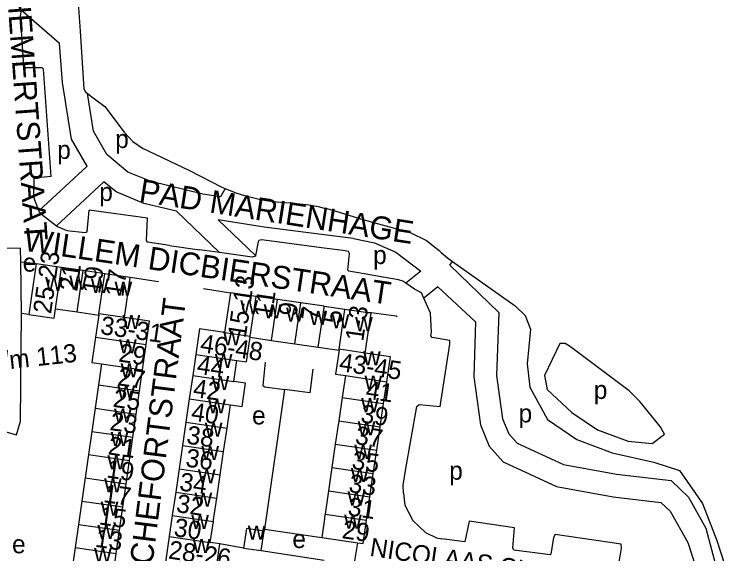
# Model space of a CAD drawing. Extents: x 160673 to 161924, y 382258 to 384145.
# Drawn here: x 161759.3 to 161915.9, y 383393.3 to 383511.4 of the extents above; entities that cross this region are included whole.
import ezdxf

# ---------------------------------------------------------------- set-up
doc = ezdxf.new("R2010")
doc.units = 0
for name, color, linetype in [('BLT_Basislijn', 7, 'Continuous'), ('BLT_Bebouwing', 7, 'Continuous'), ('BLT_Centroide', 7, 'Continuous'), ('BLT_Huisnummer', 7, 'Continuous'), ('BLT_Huisnummer_ tussenligend', 7, 'Continuous'), ('BLT_Huisnummer_reeks', 7, 'Continuous'), ('BLT_Huisnummer_zonder_bebouwing', 7, 'Continuous'), ('BLT_Onderverdeling_panden', 7, 'Continuous'), ('BLT_Straatnaam', 7, 'Continuous'), ('BLT_Straatnaam_verkleind', 7, 'Continuous')]:
    doc.layers.add(name, color=color, linetype=linetype)

msp = doc.modelspace()

# ---------------------------------------------------------------- linework, layer by layer
at = {"layer": 'BLT_Basislijn'}
for p, q in [((161773.73, 383507.7), (161774.58, 383495.12)), ((161775.28, 383478.13), (161764.67, 383468.34)), ((161778.95, 383474.72), (161768.55, 383465.12)), ((161805.49, 383473.25), (161804.45, 383471.41)), ((161804.74, 383473.57), (161805.49, 383473.25)), ((161763.77, 383470.76), (161764.67, 383468.34)), ((161794.79, 383468.29), (161804.2, 383459.25)), ((161803.95, 383466.43), (161812.11, 383458.59)), ((161845.97, 383463.66), (161849.51, 383461.89)), ((161793.31, 383460.79), (161799.89, 383459.86)), ((161764.11, 383456.74), (161760.73, 383457.16)), ((161760.91, 383445.86), (161760.73, 383457.16)), ((161854.64, 383456.49), (161855.21, 383457.31)), ((161848.28, 383455.15), (161844.99, 383452.51)), ((161790.9, 383452.81), (161784.67, 383453.8)), ((161800.73, 383451.38), (161806.64, 383450.45)), ((161848.96, 383449.28), (161848.46, 383450.45)), ((161852.04, 383451.76), (161848.96, 383449.28)), ((161852.04, 383451.76), (161860.27, 383444.06)), ((161762.52, 383445.67), (161760.91, 383445.86)), ((161818.46, 383429.21), (161814.05, 383398.67)), ((161814.05, 383398.67), (161813.99, 383398.21)), ((161814.05, 383398.67), (161826.6, 383396.85)), ((161910.64, 383398.88), (161914.28, 383385.18)), ((161833.69, 383390.85), (161834.53, 383395.69)), ((161809.5, 383394.52), (161804.33, 383395.43)), ((161813.36, 383393.96), (161827.12, 383391.85))]:
    msp.add_line(p, q, dxfattribs=at)
for points in [[(161769.48, 383567.91), (161770.84, 383548.66), (161773.73, 383507.7)], [(161767.42, 383475.92), (161765.69, 383499.42), (161765.46, 383499.68), (161761.6, 383499.66), (161761.44, 383500.07), (161760.72, 383511.06), (161760.94, 383512.21)], [(161769.9, 383496.48), (161769.19, 383505.02), (161760.94, 383512.21)], [(161775.28, 383478.13), (161771.83, 383484.08), (161769.9, 383496.48)], [(161774.58, 383495.12), (161774.93, 383494.4), (161775.33, 383494.09)], [(161804.45, 383471.41), (161800.59, 383472.04), (161789.26, 383474.76), (161784.21, 383476.87), (161779.57, 383480.68), (161776.63, 383485.78), (161775.33, 383494.09)], [(161775.33, 383494.09), (161776.89, 383492.92), (161779.13, 383491.2), (161783.37, 383485.58), (161785.3, 383483.55), (161787.4, 383482.08), (161797.7, 383477.21), (161804.74, 383473.57)], [(161767.42, 383475.92), (161763.57, 383475.53), (161763.52, 383471.55), (161763.77, 383470.76)], [(161794.79, 383468.29), (161787.7, 383469.99), (161781.6, 383472.54), (161778.95, 383474.72)], [(161805.49, 383473.25), (161806.38, 383472.88), (161808.05, 383472.26), (161809.74, 383471.72), (161811.46, 383471.26), (161813.19, 383470.87), (161814.94, 383470.57), (161816.7, 383470.34), (161818.47, 383470.19), (161819.84, 383470.13)], [(161819.84, 383470.13), (161821.84, 383469.93), (161823.82, 383469.65), (161825.79, 383469.29), (161827.12, 383468.99)], [(161764.67, 383468.34), (161764.72, 383468.2), (161765.26, 383467.62), (161768.55, 383465.12)], [(161769.82, 383464.48), (161770.81, 383464.07), (161774.87, 383463.65), (161775.3, 383463.76), (161775.75, 383468.54)], [(161793.31, 383460.79), (161788.46, 383461.51), (161788.25, 383461.86), (161788.48, 383466.8), (161775.75, 383468.54)], [(161827.12, 383468.99), (161827.74, 383468.85), (161829.67, 383468.33), (161831.15, 383467.88)], [(161831.15, 383467.88), (161835.09, 383466.65), (161839.05, 383465.49), (161843.03, 383464.41), (161845.97, 383463.66)], [(161827.12, 383463.12), (161813.99, 383464.79), (161803.95, 383466.43)], [(161768.55, 383465.12), (161768.91, 383464.84), (161769.82, 383464.48)], [(161833.55, 383462.3), (161827.12, 383463.12)], [(161827.12, 383460.19), (161813.39, 383462.01), (161812.84, 383461.85), (161812.68, 383461.58), (161812.11, 383458.59)], [(161833.55, 383462.3), (161838.17, 383461.39), (161842.8, 383459.29), (161848.28, 383455.15)], [(161849.51, 383461.89), (161850.91, 383460.81), (161852.27, 383459.67), (161852.76, 383459.24)], [(161760.73, 383457.16), (161760.68, 383460.22), (161757.04, 383460.11)], [(161804.2, 383459.25), (161799.89, 383459.86)], [(161843.43, 383453.29), (161832.51, 383455.14), (161832.35, 383455.36), (161832.67, 383459.04), (161832.46, 383459.43), (161831.23, 383459.65), (161827.12, 383460.19)], [(161812.11, 383458.59), (161812.08, 383458.44), (161811.35, 383458.23), (161804.2, 383459.25)], [(161852.76, 383459.24), (161854.16, 383458.06), (161855.21, 383457.31)], [(161855.21, 383457.31), (161868.9, 383447.57)], [(161854.64, 383456.49), (161865.34, 383446.1), (161864.87, 383432.31), (161866.19, 383422.83), (161867.54, 383419.57), (161869.37, 383417.51), (161879.51, 383412.83), (161891.11, 383410.67), (161903.04, 383409.3), (161906.83, 383405.7), (161910.64, 383398.88)], [(161844.99, 383452.51), (161844.32, 383452.96), (161843.43, 383453.29)], [(161848.46, 383450.45), (161846.9, 383451.23), (161844.99, 383452.51)], [(161844.94, 383411.51), (161847.42, 383425.5), (161847.9, 383425.93), (161852.49, 383425.5), (161854.66, 383439.16), (161854.66, 383439.95), (161850.77, 383440.66), (161850.45, 383441.02), (161850.64, 383441.77), (161850.37, 383445.93), (161848.96, 383449.28)], [(161868.9, 383447.57), (161871.11, 383445.45), (161872.28, 383442.49), (161871.58, 383434.88), (161872.11, 383429.73), (161875.98, 383422.7), (161882.42, 383418.32), (161890.17, 383415.35), (161899.31, 383413.34), (161904.86, 383411.54), (161909.91, 383404.26), (161913.04, 383396.17)], [(161751.76, 383403.06), (161756.44, 383420.27), (161759.83, 383419.35), (161760.67, 383422.31), (161760.91, 383445.86)], [(161843.12, 383445.13), (161842.91, 383445.3), (161837.41, 383446.03)], [(161860.27, 383444.06), (161859.86, 383432.05), (161861.33, 383421.51), (161863.25, 383416.87), (161866.33, 383413.41), (161877.98, 383408.03), (161890.36, 383405.72), (161900.81, 383404.52), (161902.83, 383402.6), (161906.69, 383395.71)], [(161814.24, 383435.22), (161813.7, 383430.09), (161814.18, 383429.82), (161818.46, 383429.21)], [(161824.69, 383433.7), (161824.03, 383428.54), (161818.46, 383429.21)], [(161844.48, 383406.57), (161844.45, 383408.31), (161844.94, 383411.51)], [(161844.48, 383406.57), (161844.78, 383403.95), (161846.53, 383400.54), (161849.3, 383397.9), (161851.74, 383396.77), (161852.92, 383396.53)], [(161858.84, 383400.41), (161857.91, 383395.86), (161852.92, 383396.53)], [(161906.73, 383383.61), (161905.69, 383387.62), (161900, 383388.49), (161891.56, 383390.53), (161892.17, 383394.49), (161892.14, 383395.41), (161877.7, 383397.48), (161877.33, 383396.85), (161876.77, 383393.18), (161876.62, 383393.02), (161868.62, 383394.06), (161868.41, 383394.58), (161868.79, 383398.92), (161858.84, 383400.41)], [(161906.69, 383395.71), (161908.37, 383390.55), (161909.71, 383382.11), (161909.71, 383375.2), (161910.5, 383367.55), (161911.76, 383360.3), (161913.12, 383353.69), (161913.12, 383350.66), (161912.25, 383346.91)], [(161913.04, 383396.17), (161914.76, 383391.02), (161915.88, 383385.88)]]:
    msp.add_lwpolyline(points, dxfattribs=at)
msp.add_lwpolyline([(161878.7, 383439.34), (161875.34, 383432.33), (161875.93, 383429.28), (161881.3, 383424.18), (161886.96, 383420.4), (161893.66, 383417.95), (161898.94, 383417.45), (161901.58, 383419.45), (161900.66, 383421.17), (161896.18, 383426.59), (161893.9, 383428.92), (161881.01, 383438.58), (161879.9, 383439.35)], close=True, dxfattribs=at)
at = {"layer": 'BLT_Bebouwing'}
for p, q in [((161769.63, 383455.95), (161764.11, 383456.74)), ((161774.39, 383455.27), (161769.63, 383455.95)), ((161779.12, 383454.59), (161774.39, 383455.27)), ((161784.67, 383453.8), (161779.12, 383454.59)), ((161783.41, 383445.01), (161784.67, 383453.8)), ((161806.64, 383450.45), (161805.36, 383441.74)), ((161812.23, 383449.63), (161806.64, 383450.45)), ((161816.89, 383448.95), (161812.23, 383449.63)), ((161822.02, 383448.2), (161816.89, 383448.95)), ((161827.12, 383447.46), (161822.02, 383448.2)), ((161827.15, 383447.45), (161827.12, 383447.46)), ((161831.68, 383446.79), (161827.15, 383447.45)), ((161768.33, 383446.9), (161773.09, 383446.22)), ((161773.09, 383446.22), (161777.82, 383445.54)), ((161836.12, 383437.2), (161837.41, 383446.03)), ((161777.82, 383445.54), (161777.13, 383440.72)), ((161810.92, 383440.68), (161815.58, 383440)), ((161815.58, 383440), (161820.71, 383439.25)), ((161787.39, 383433.58), (161788.19, 383439.13)), ((161820.71, 383439.25), (161825.84, 383438.5)), ((161799.06, 383436.94), (161798.38, 383432.32)), ((161841.62, 383436.4), (161836.12, 383437.2)), ((161840.83, 383430.96), (161841.62, 383436.4)), ((161778.44, 383434.86), (161777.78, 383430.24)), ((161807.37, 383431.01), (161808.05, 383435.62)), ((161786.73, 383428.96), (161787.39, 383433.58)), ((161798.38, 383432.32), (161797.63, 383427.22)), ((161831.77, 383432.28), (161831.08, 383427.5)), ((161777.78, 383430.24), (161777.05, 383425.15)), ((161840.13, 383426.18), (161840.83, 383430.96)), ((161786, 383423.87), (161786.73, 383428.96)), ((161797.63, 383427.22), (161796.89, 383422.11)), ((161831.08, 383427.5), (161830.33, 383422.39)), ((161805.88, 383420.8), (161806.62, 383425.9)), ((161839.39, 383421.07), (161840.13, 383426.18)), ((161777.05, 383425.15), (161776.32, 383420.07)), ((161785.27, 383418.78), (161786, 383423.87)), ((161830.33, 383422.39), (161829.58, 383417.28)), ((161796.89, 383422.11), (161796.14, 383417)), ((161805.13, 383415.69), (161805.88, 383420.8)), ((161838.64, 383415.96), (161839.39, 383421.07)), ((161776.32, 383420.07), (161775.59, 383414.98)), ((161784.54, 383413.69), (161785.27, 383418.78)), ((161796.14, 383417), (161795.4, 383411.89)), ((161829.58, 383417.28), (161828.84, 383412.17)), ((161837.89, 383410.85), (161838.64, 383415.96)), ((161775.59, 383414.98), (161774.87, 383409.89)), ((161804.39, 383410.58), (161805.13, 383415.69)), ((161783.81, 383408.61), (161784.54, 383413.69)), ((161795.4, 383411.89), (161794.65, 383406.78)), ((161828.84, 383412.17), (161828.09, 383407.07)), ((161774.87, 383409.89), (161774.14, 383404.8)), ((161803.64, 383405.47), (161804.39, 383410.58)), ((161837.15, 383405.74), (161837.89, 383410.85)), ((161783.09, 383403.52), (161783.81, 383408.61)), ((161794.65, 383406.78), (161793.9, 383401.68)), ((161828.09, 383407.07), (161827.34, 383401.96)), ((161836.4, 383400.63), (161837.15, 383405.74)), ((161774.14, 383404.8), (161773.41, 383399.71)), ((161782.36, 383398.43), (161783.09, 383403.52)), ((161793.9, 383401.68), (161793.23, 383397.06)), ((161802.22, 383395.74), (161802.89, 383400.36)), ((161773.41, 383399.71), (161772.68, 383394.62)), ((161781.63, 383393.34), (161782.36, 383398.43)), ((161813.36, 383393.96), (161813.99, 383398.21)), ((161793.23, 383397.06), (161792.41, 383391.46)), ((161804.33, 383395.43), (161802.22, 383395.74)), ((161826.6, 383396.85), (161827.12, 383396.77)), ((161827.12, 383396.77), (161834.53, 383395.69)), ((161772.68, 383394.62), (161771.95, 383389.54)), ((161809.5, 383394.52), (161813.36, 383393.96)), ((161780.9, 383388.26), (161781.63, 383393.34))]:
    msp.add_line(p, q, dxfattribs=at)
for points in [[(161764.11, 383456.74), (161763.4, 383451.79), (161762.52, 383445.67)], [(161762.52, 383445.67), (161768.04, 383444.88), (161768.33, 383446.9)], [(161837.41, 383446.03), (161836.71, 383446.06), (161831.68, 383446.79)], [(161788.19, 383439.13), (161788.92, 383444.22), (161783.41, 383445.01)], [(161805.36, 383441.74), (161799.87, 383442.54), (161799.06, 383436.94)], [(161777.13, 383440.72), (161776.33, 383435.17), (161778.44, 383434.86)], [(161808.05, 383435.62), (161810.14, 383435.32), (161810.92, 383440.68)], [(161825.84, 383438.5), (161830.42, 383437.83)], [(161830.42, 383437.83), (161829.65, 383432.59), (161831.77, 383432.28)], [(161806.62, 383425.9), (161809.19, 383425.53), (161809.93, 383430.64), (161807.37, 383431.01)], [(161802.89, 383400.36), (161802.94, 383400.69), (161803.64, 383405.47)], [(161827.34, 383401.96), (161827.32, 383401.8), (161827.12, 383400.4)], [(161827.12, 383400.4), (161826.6, 383396.85)], [(161834.53, 383395.69), (161835.65, 383395.52), (161836.4, 383400.63)], [(161813.99, 383398.21), (161810.13, 383398.78), (161809.5, 383394.52)], [(161792.41, 383391.46), (161803.51, 383389.84), (161804.33, 383395.43)]]:
    msp.add_lwpolyline(points, dxfattribs=at)
at = {"layer": 'BLT_Onderverdeling_panden'}
for p, q in [((161768.33, 383446.9), (161769.63, 383455.95)), ((161773.09, 383446.22), (161774.39, 383455.27)), ((161777.86, 383445.81), (161779.12, 383454.59)), ((161810.96, 383440.92), (161812.23, 383449.63)), ((161815.58, 383440), (161816.89, 383448.95)), ((161820.71, 383439.25), (161822.02, 383448.2)), ((161825.84, 383438.5), (161827.12, 383447.23)), ((161827.12, 383447.23), (161827.15, 383447.45)), ((161777.82, 383445.54), (161777.86, 383445.81)), ((161783.41, 383445.01), (161777.86, 383445.81)), ((161805.36, 383441.74), (161810.96, 383440.92)), ((161810.92, 383440.68), (161810.96, 383440.92)), ((161777.13, 383440.72), (161788.19, 383439.13)), ((161830.42, 383437.83), (161830.42, 383438.11)), ((161799.06, 383436.94), (161808.05, 383435.62)), ((161778.44, 383434.86), (161787.39, 383433.58)), ((161798.38, 383432.32), (161807.37, 383431.01)), ((161831.77, 383432.28), (161840.83, 383430.96)), ((161777.78, 383430.24), (161786.73, 383428.96)), ((161797.63, 383427.22), (161806.62, 383425.9)), ((161831.08, 383427.5), (161840.13, 383426.18)), ((161777.05, 383425.15), (161786, 383423.87)), ((161830.33, 383422.39), (161839.39, 383421.07)), ((161796.89, 383422.11), (161805.88, 383420.8)), ((161776.32, 383420.07), (161785.27, 383418.78)), ((161796.14, 383417), (161805.13, 383415.69)), ((161829.58, 383417.28), (161838.64, 383415.96)), ((161775.59, 383414.98), (161784.54, 383413.69)), ((161795.4, 383411.89), (161804.39, 383410.58)), ((161828.84, 383412.17), (161837.89, 383410.85)), ((161774.87, 383409.89), (161783.81, 383408.61)), ((161794.65, 383406.78), (161803.64, 383405.47)), ((161828.09, 383407.07), (161837.15, 383405.74)), ((161774.14, 383404.8), (161783.09, 383403.52)), ((161827.34, 383401.96), (161836.4, 383400.63)), ((161793.9, 383401.68), (161802.89, 383400.36)), ((161773.41, 383399.71), (161782.36, 383398.43)), ((161793.23, 383397.06), (161802.22, 383395.74)), ((161772.68, 383394.62), (161781.63, 383393.34))]:
    msp.add_line(p, q, dxfattribs=at)
for points in [[(161830.42, 383438.11), (161831.68, 383446.79)], [(161836.12, 383437.2), (161830.42, 383438.11)]]:
    msp.add_lwpolyline(points, dxfattribs=at)

# ---------------------------------------------------------------- texts
at = {"layer": 'BLT_Centroide'}
for s, p in [('p', (161781.41, 383482.12)), ('p', (161768.72, 383479.74)), ('p', (161777.93, 383470.53)), ('p', (161837.85, 383456.72)), ('e', (161761.17, 383455.05)), ('w', (161766.08, 383450.81)), ('w', (161771.36, 383451.08)), ('w', (161776.11, 383450.41)), ('w', (161781.27, 383449.8)), ('w', (161808.8, 383445.69)), ('w', (161813.91, 383444.81)), ('w', (161818.8, 383444.11)), ('w', (161823.92, 383443.36)), ('w', (161828.77, 383442.64)), ('w', (161783.02, 383442.47)), ('w', (161833.91, 383442.02)), ('w', (161805.01, 383438.94)), ('w', (161782.26, 383437.16)), ('w', (161803.21, 383433.97)), ('w', (161835.65, 383434.53)), ('w', (161782.59, 383431.91)), ('w', (161802.5, 383429.12)), ('w', (161835.95, 383429.22)), ('w', (161781.89, 383427.06)), ('p', (161886.14, 383427.17)), ('w', (161801.76, 383424)), ('w', (161835.23, 383424.28)), ('w', (161781.16, 383421.97)), ('e', (161811.36, 383421.6)), ('p', (161869.68, 383422.03)), ('w', (161834.48, 383419.19)), ('w', (161801.02, 383418.91)), ('w', (161780.43, 383416.88)), ('w', (161800.27, 383413.78)), ('w', (161833.73, 383414.06)), ('w', (161779.7, 383411.78)), ('w', (161799.52, 383408.69)), ('w', (161832.98, 383408.97)), ('p', (161854.5, 383409.49)), ('w', (161778.98, 383406.72)), ('w', (161798.77, 383403.56)), ('w', (161832.25, 383403.84)), ('w', (161778.24, 383401.62)), ('w', (161798.06, 383398.72)), ('w', (161831.5, 383398.75)), ('w', (161777.52, 383396.53)), ('w', (161810.42, 383396.36)), ('e', (161820.18, 383394.53)), ('e', (161758.84, 383393.38)), ('w', (161798.38, 383393.44)), ('w', (161776.79, 383391.44))]:
    msp.add_text(s, height=4, dxfattribs=at).set_placement(p)
at = {"layer": 'BLT_Huisnummer'}
for s, rotation, p in [('21', 81.8424, (161773.1, 383450.59)), ('17', 81.8443, (161783.15, 383449.37)), ('9', 81.689, (161821.06, 383445.12)), ('5', 81.6899, (161830.78, 383443.46)), ('29', 351.8412, (161781.99, 383435.39)), ('42', 351.6906, (161798.29, 383427.65)), ('41', 351.6884, (161836.07, 383427.28)), ('25', 351.8412, (161780.77, 383425.47)), ('38', 351.6897, (161796.86, 383417.42)), ('37', 351.6884, (161833.78, 383417.33)), ('21', 351.8412, (161779.68, 383415.07)), ('34', 351.6897, (161795.3, 383407.16)), ('33', 351.6893, (161832.35, 383406.82)), ('17', 351.8412, (161778.68, 383404.59)), ('30', 351.6897, (161794.09, 383397.17)), ('29', 351.6893, (161830.87, 383396.71)), ('13', 351.8466, (161776.86, 383394.82))]:
    msp.add_text(s, height=4, rotation=rotation, dxfattribs=at).set_placement(p)
at = {"layer": 'BLT_Huisnummer_ tussenligend'}
for s, rotation, p in [('19', 81.8443, (161778.08, 383450.05)), ('11', 81.6899, (161815.68, 383444.77)), ('7', 81.6899, (161826.04, 383444.13)), ('44', 351.6906, (161799.12, 383432.73)), ('27', 351.8412, (161781.77, 383430.21)), ('40', 351.6897, (161797.87, 383422.5)), ('39', 351.6884, (161834.97, 383422.07)), ('23', 351.8412, (161780.08, 383420.39)), ('36', 351.6897, (161796.65, 383412.41)), ('35', 351.6893, (161833.02, 383411.9)), ('19', 351.8412, (161779.37, 383410.01)), ('32', 351.6897, (161794.61, 383402.42)), ('31', 351.6893, (161832.17, 383401.72)), ('15', 351.8466, (161777.71, 383399.73))]:
    msp.add_text(s, height=4, rotation=rotation, dxfattribs=at).set_placement(p)
at = {"layer": 'BLT_Huisnummer_reeks'}
for s, rotation, p in [('25-23', 81.8424, (161767.36, 383445.68)), ('15-13', 81.689, (161809.96, 383440.4)), ('1-3', 81.6895, (161835.67, 383439.65)), ('33-31', 351.8452, (161778.01, 383441.41)), ('46-48', 351.6906, (161799.85, 383437.46)), ('43-45', 351.6893, (161830.25, 383433.32)), ('28-26', 351.6886, (161792.89, 383392.25))]:
    msp.add_text(s, height=4, rotation=rotation, dxfattribs=at).set_placement(p)
at = {"layer": 'BLT_Huisnummer_zonder_bebouwing'}
msp.add_text('21 73 t/m 113', height=4, rotation=6.2774, dxfattribs=at).set_placement((161740.69, 383431.76))
at = {"layer": 'BLT_Straatnaam'}
for s, height, rotation, p in [('ANTONIE VAN HEMERTSTRAAT', 5, 274.147, (161754.33, 383563.14)), ('PAD MARIENHAGE', 5, 351.1364, (161786.44, 383470.42)), ('WILLEM DICBIERSTRAAT', 4.9999, 351.5498, (161761.18, 383459.68)), ('JOHANNA VAN ROCHEFORTSTRAAT', 5, 82.7709, (161782.06, 383331.69)), ('NICOLAAS CLOPPERSTRAAT', 4, 351.5952, (161836.96, 383392.83))]:
    msp.add_text(s, height=height, rotation=rotation, dxfattribs=at).set_placement(p)
at = {"layer": 'BLT_Straatnaam_verkleind'}
msp.add_text('HUBERT SEIJSSEMAECKERSTRAAT', height=4, rotation=4.0719, dxfattribs=at).set_placement((161677.66, 383509.79))

doc.saveas('drawing.dxf')
